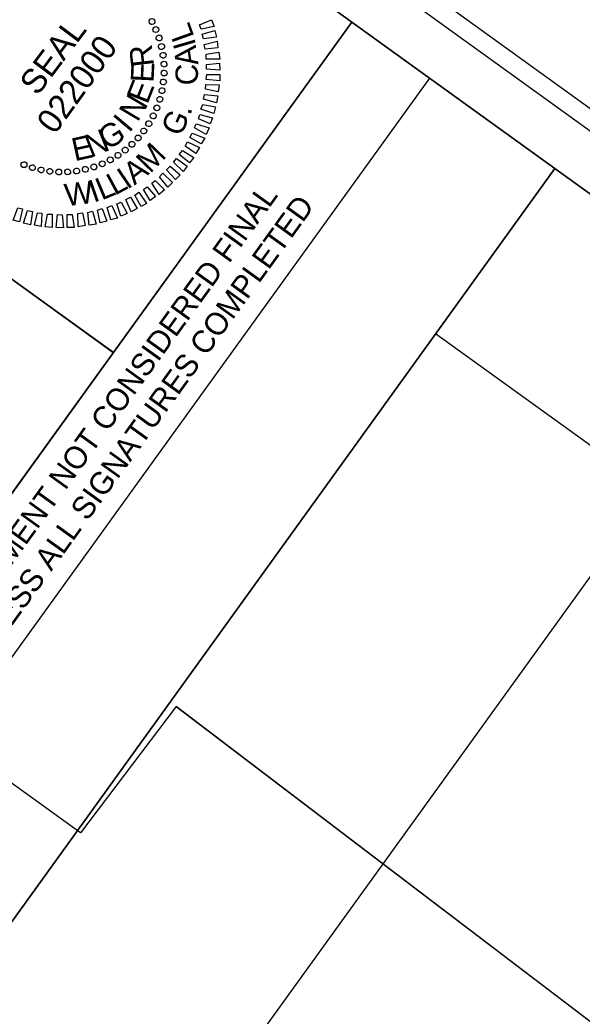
# Model space of a CAD drawing. Extents: x 2189185 to 2191058, y 386509 to 388561.
# Drawn here: x 2190218.6 to 2190356.5, y 388156.8 to 388401.3 of the extents above; entities that cross this region are included whole.
import ezdxf

# ---------------------------------------------------------------- set-up
doc = ezdxf.new("R2010")
doc.units = 0
for name, color, linetype in [('Matchline', 7, 'Continuous'), ('Sheet Clip Boundary CELL', 7, 'Continuous'), ('Sheet Layout Plan Border', 7, 'Continuous'), ('Sheet Plan CELL', 7, 'Continuous'), ('Sheet Plan Layout CELL', 7, 'Continuous'), ('Sheet Plot Border Inside CELL', 7, 'Continuous'), ('Sheet Plot Border Outside CELL', 7, 'Continuous'), ('Sheet Professional Seal CELL', 7, 'Continuous'), ('Sheet Sticker Exception Certification CELL', 7, 'Continuous')]:
    doc.layers.add(name, color=color, linetype=linetype)

msp = doc.modelspace()

# ---------------------------------------------------------------- linework, layer by layer
at = {"layer": 'Matchline'}
msp.add_line((2190256.9, 388232.77), (2190718.7, 387881.07), dxfattribs=at)
at = {"layer": 'Sheet Clip Boundary CELL'}
msp.add_lwpolyline([(2190166.8, 386710.01), (2190905.33, 387738.93), (2190256.9, 388232.77), (2190233.39, 388201.76), (2190061.07, 388326.03), (2189853.58, 388001.31), (2189912.61, 387915.43), (2189757.61, 387710.51), (2189654.64, 387750.49), (2189330.08, 387312.42)], close=True, dxfattribs=at)
at = {"layer": 'Sheet Layout Plan Border'}
for points in [[(2190188.92, 387222.15), (2189805.85, 387498.41), (2190526.13, 388497.18), (2190654.9, 388404.31), (2190753.52, 388541.06), (2191007.82, 388357.66)], [(2190181.72, 386698.24), (2191000.63, 387833.76), (2190320.53, 388324.24), (2190209.82, 388170.73), (2190038.29, 388294.44), (2189330.08, 387312.42)]]:
    msp.add_lwpolyline(points, close=True, dxfattribs=at)
at = {"layer": 'Sheet Plan CELL'}
msp.add_line((2190150.21, 388385.42), (2190241.44, 388319.64), dxfattribs=at)
for points in [[(2190178.25, 388488.52), (2189300.83, 387271.86), (2190152.47, 386657.68), (2191029.88, 387874.32)], [(2190150.21, 388385.42), (2190208.69, 388466.52), (2190299.95, 388400.72), (2190241.47, 388319.6)], [(2190152.47, 386657.68), (2189300.84, 387271.83), (2190061.21, 388326.25), (2190182.93, 388238.48), (2190299.95, 388400.72), (2191029.88, 387874.32)], [(2190091.69, 388304.27), (2190150.21, 388385.42), (2190241.47, 388319.6), (2190182.93, 388238.48)]]:
    msp.add_lwpolyline(points, close=True, dxfattribs=at)
at = {"layer": 'Sheet Plan Layout CELL'}
for points in [[(2190209.82, 388170.73), (2190349.78, 388364.8), (2190178.26, 388488.53), (2190038.29, 388294.44)], [(2189300.84, 387271.83), (2190152.47, 386657.68), (2191029.87, 387874.31), (2190349.77, 388364.78), (2190209.82, 388170.73), (2190038.29, 388294.44)]]:
    msp.add_lwpolyline(points, close=True, dxfattribs=at)
at = {"layer": 'Sheet Plot Border Inside CELL'}
msp.add_lwpolyline([(2190064.73, 386531.72), (2191039.21, 387882.98), (2190183.53, 388500.09), (2189209.04, 387148.83)], close=True, dxfattribs=at)
at = {"layer": 'Sheet Plot Border Outside CELL'}
msp.add_lwpolyline([(2190073.35, 386509.48), (2191058.08, 387874.94), (2190169.94, 388515.44), (2189185.21, 387149.98)], close=True, dxfattribs=at)
at = {"layer": 'Sheet Professional Seal CELL'}
for p, q in [((2190250.97, 388400.87), (2190250.97, 388400.87)), ((2190251.97, 388398.92), (2190251.97, 388398.92)), ((2190252.7, 388396.85), (2190252.7, 388396.85)), ((2190253.33, 388394.73), (2190253.33, 388394.73)), ((2190253.71, 388392.61), (2190253.71, 388392.61)), ((2190228.86, 388389.01), (2190228.86, 388389.01)), ((2190253.95, 388388.24), (2190253.95, 388388.24)), ((2190253.96, 388390.39), (2190253.96, 388390.39)), ((2190253.77, 388386.03), (2190253.77, 388386.03)), ((2190253.44, 388383.86), (2190253.44, 388383.86)), ((2190252.92, 388381.77), (2190252.92, 388381.77)), ((2190252.18, 388379.72), (2190252.18, 388379.72)), ((2190251.22, 388377.7), (2190251.22, 388377.7)), ((2190248.96, 388373.97), (2190248.96, 388373.97)), ((2190250.2, 388375.78), (2190250.2, 388375.78)), ((2190247.55, 388372.27), (2190247.55, 388372.27)), ((2190244.41, 388369.29), (2190244.41, 388369.29)), ((2190246.01, 388370.73), (2190246.01, 388370.73)), ((2190240.72, 388366.9), (2190240.72, 388366.9)), ((2190242.62, 388368), (2190242.62, 388368)), ((2190219.56, 388365.7), (2190219.56, 388365.7)), ((2190221.62, 388364.95), (2190221.62, 388364.95)), ((2190223.71, 388364.43), (2190223.71, 388364.43)), ((2190225.88, 388364.1), (2190225.88, 388364.1)), ((2190228.09, 388363.93), (2190228.09, 388363.93)), ((2190230.24, 388363.92), (2190230.24, 388363.92)), ((2190232.46, 388364.17), (2190232.46, 388364.17)), ((2190234.58, 388364.55), (2190234.58, 388364.55)), ((2190236.7, 388365.18), (2190236.7, 388365.18)), ((2190238.76, 388365.91), (2190238.76, 388365.91))]:
    msp.add_line(p, q, dxfattribs=at)
for points in [[(2190262.6, 388400.07), (2190265.56, 388401.26), (2190266.18, 388399.64), (2190262.99, 388398.98)], [(2190263.26, 388397.74), (2190266.37, 388398.71), (2190266.78, 388397.05), (2190263.58, 388396.65)], [(2190263.78, 388395.21), (2190266.93, 388396.08), (2190267.14, 388394.39), (2190263.96, 388394.09)], [(2190264.23, 388392.85), (2190267.31, 388393.34), (2190267.58, 388391.67), (2190264.25, 388391.67)], [(2190264.32, 388390.32), (2190267.53, 388390.66), (2190267.59, 388388.95), (2190264.29, 388389.17)], [(2190264.43, 388387.9), (2190267.58, 388387.91), (2190267.59, 388386.3), (2190264.27, 388386.66)], [(2190264.15, 388385.38), (2190267.43, 388385.31), (2190267.17, 388383.58), (2190264.09, 388384.26)], [(2190263.87, 388382.94), (2190267.08, 388382.6), (2190266.74, 388380.93), (2190263.59, 388381.78)], [(2190263.43, 388380.54), (2190266.55, 388379.9), (2190266.16, 388378.33), (2190262.95, 388379.35)], [(2190262.65, 388378.08), (2190265.76, 388377.26), (2190265.21, 388375.74), (2190262.32, 388377.03)], [(2190260.82, 388373.49), (2190263.88, 388372.27), (2190263.04, 388370.84), (2190260.24, 388372.43)], [(2190261.77, 388375.76), (2190264.94, 388374.77), (2190264.23, 388373.18), (2190261.36, 388374.76)], [(2190259.66, 388371.37), (2190262.57, 388369.94), (2190261.74, 388368.45), (2190259.08, 388370.31)], [(2190258.4, 388369.19), (2190261.18, 388367.5), (2190260.17, 388366.19), (2190257.65, 388368.25)], [(2190256.95, 388367.28), (2190259.59, 388365.37), (2190258.58, 388364.07), (2190256.21, 388366.33)], [(2190255.37, 388365.34), (2190257.89, 388363.27), (2190256.68, 388362.11), (2190254.5, 388364.48)], [(2190251.7, 388361.88), (2190254.05, 388359.57), (2190252.73, 388358.43), (2190250.88, 388361.17)], [(2190253.64, 388363.62), (2190255.97, 388361.39), (2190254.8, 388360.19), (2190252.82, 388362.74)], [(2190247.72, 388359.01), (2190249.61, 388356.24), (2190248.3, 388355.45), (2190246.77, 388358.28)], [(2190249.77, 388360.31), (2190251.85, 388357.89), (2190250.53, 388356.92), (2190248.87, 388359.66)], [(2190243.36, 388356.55), (2190244.88, 388353.79), (2190243.31, 388353.07), (2190242.32, 388356.13)], [(2190245.64, 388357.74), (2190247.3, 388355), (2190245.83, 388354.16), (2190244.55, 388357.17)], [(2190219.2, 388354.93), (2190218.47, 388351.69), (2190216.89, 388352.15), (2190218.05, 388355.14)], [(2190221.63, 388354.28), (2190221.12, 388351.01), (2190219.44, 388351.42), (2190220.44, 388354.52)], [(2190223.96, 388353.84), (2190223.74, 388350.54), (2190222.1, 388350.92), (2190222.84, 388353.91)], [(2190233.87, 388353.9), (2190234.52, 388350.78), (2190232.84, 388350.51), (2190232.78, 388353.76)], [(2190236.34, 388354.34), (2190237.25, 388351.15), (2190235.57, 388350.88), (2190235.18, 388354.01)], [(2190238.71, 388354.97), (2190239.86, 388351.86), (2190238.2, 388351.45), (2190237.59, 388354.61)], [(2190241.12, 388355.76), (2190242.45, 388352.64), (2190240.84, 388352.2), (2190239.99, 388355.22)], [(2190226.5, 388353.6), (2190226.49, 388350.34), (2190224.72, 388350.45), (2190225.28, 388353.62)], [(2190228.93, 388353.46), (2190229.2, 388350.24), (2190227.46, 388350.32), (2190227.8, 388353.53)], [(2190231.38, 388353.54), (2190231.86, 388350.35), (2190230.15, 388350.29), (2190230.16, 388353.55)]]:
    msp.add_lwpolyline(points, close=True, dxfattribs=at)
for centre, major_axis in [((2190250.96, 388400.87), (0.635, 0.34)), ((2190251.91, 388398.9), (0.662, 0.284)), ((2190252.69, 388396.85), (0.684, 0.225)), ((2190253.28, 388394.74), (0.701, 0.164)), ((2190253.68, 388392.59), (0.713, 0.103)), ((2190253.9, 388390.42), (0.719, 0.04)), ((2190253.93, 388388.23), (0.72, -0.023)), ((2190253.76, 388386.05), (0.715, -0.085)), ((2190253.41, 388383.89), (0.705, -0.147)), ((2190252.87, 388381.77), (0.689, -0.208)), ((2190251.25, 388377.71), (0.643, -0.325)), ((2190252.15, 388379.7), (0.669, -0.267)), ((2190250.18, 388375.8), (0.612, -0.379)), ((2190248.94, 388373.99), (0.577, -0.431)), ((2190246.03, 388370.73), (0.493, -0.525)), ((2190247.56, 388372.3), (0.537, -0.48)), ((2190242.59, 388368.03), (0.394, -0.602)), ((2190244.37, 388369.31), (0.445, -0.566)), ((2190219.55, 388365.73), (-0.267, -0.669)), ((2190238.74, 388365.96), (0.284, -0.662)), ((2190240.71, 388366.91), (0.34, -0.635)), ((2190221.61, 388365), (-0.208, -0.689)), ((2190223.73, 388364.46), (-0.147, -0.705)), ((2190225.89, 388364.11), (-0.085, -0.715)), ((2190228.07, 388363.95), (-0.023, -0.72)), ((2190230.26, 388363.97), (0.04, -0.719)), ((2190232.44, 388364.19), (0.103, -0.713)), ((2190234.59, 388364.6), (0.164, -0.701)), ((2190236.69, 388365.19), (0.225, -0.684))]:
    msp.add_ellipse(centre, major_axis=major_axis, ratio=0.999708, dxfattribs=at)
at = {"layer": 'Sheet Sticker Exception Certification CELL'}
for p, q in [((2190182.93, 388238.48), (2190299.94, 388400.73)), ((2190182.93, 388238.48), (2190299.94, 388400.73)), ((2190299.95, 388400.72), (2190319.01, 388386.97)), ((2190299.95, 388400.72), (2190319.01, 388386.97)), ((2190319, 388386.98), (2190201.99, 388224.74)), ((2190319, 388386.98), (2190201.99, 388224.74))]:
    msp.add_line(p, q, dxfattribs=at)

# ---------------------------------------------------------------- texts
at = {"layer": 'Sheet Professional Seal CELL'}
for s, height, rotation, p in [('L', 5.5, 109.802, (2190261.4, 388397.14)), ('SEAL', 5.998, 53.2018, (2190222.87, 388382.42)), ('022000', 5.998, 54.2018, (2190227.12, 388372.91)), ('I', 5.5, 106.2815, (2190261.83, 388395.12)), ('R', 5.64, 96.6833, (2190251.5, 388390.07)), ('A', 5.5, 98.0957, (2190262.37, 388390.37)), ('E', 5.64, 87.3259, (2190251.33, 388385.81)), ('C', 5.5, 89.223, (2190262.18, 388385.18)), ('E', 5.64, 68.6136, (2190249.82, 388380.37)), ('N', 5.64, 59.2582, (2190247.41, 388376.01)), ('G', 5.5, 66.111, (2190258, 388372.41)), ('.', 5.5, 76.0427, (2190260.42, 388377.69)), ('G', 5.64, 31.1921, (2190239.95, 388369.18)), ('I', 5.64, 49.903, (2190245.33, 388373.38)), ('N', 5.64, 21.8358, (2190235.91, 388367.41)), ('E', 5.64, 12.4787, (2190231.96, 388366.56)), ('M', 5.5, 45.99, (2190250.51, 388363.4)), ('A', 5.5, 37.8042, (2190246.64, 388360.58)), ('I', 5.5, 34.2837, (2190244.86, 388359.54)), ('W', 5.5, 7.5368, (2190229.89, 388355.5)), ('I', 5.5, 19.1429, (2190236.61, 388356.39)), ('L', 5.5, 22.6633, (2190238.6, 388356.92)), ('L', 5.5, 28.4735, (2190241.8, 388358.08))]:
    msp.add_text(s, height=height, rotation=rotation, dxfattribs=at).set_placement(p)
at = {"layer": 'Sheet Sticker Exception Certification CELL'}
for s, p in [('DOCUMENT NOT CONSIDERED FINAL', (2190203.65, 388249.52)), ('DOCUMENT NOT CONSIDERED FINAL', (2190203.65, 388249.52)), ('UNLESS ALL SIGNATURES COMPLETED', (2190207.82, 388240.26)), ('UNLESS ALL SIGNATURES COMPLETED', (2190207.82, 388240.26))]:
    msp.add_text(s, height=5.5, rotation=54.2018, dxfattribs=at).set_placement(p)

doc.saveas('drawing.dxf')
